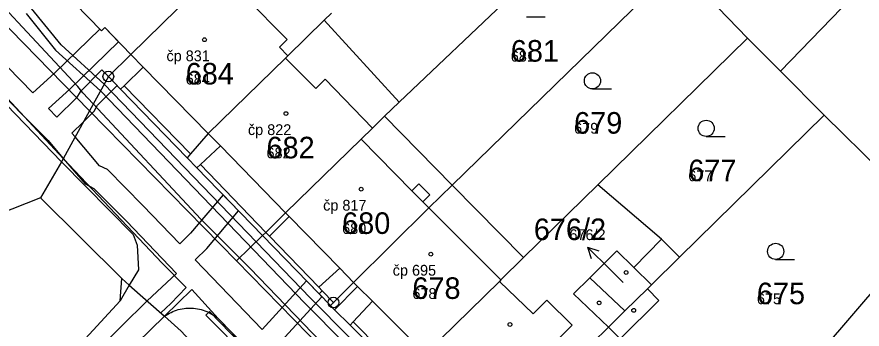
# Model space of a CAD drawing. Extents: x -763628 to -761565, y -976033 to -973833.
# Drawn here: x -762200.4 to -762122, y -974541.7 to -974512.8 of the extents above; entities that cross this region are included whole.
import ezdxf

# ---------------------------------------------------------------- set-up
doc = ezdxf.new("R2010")
doc.units = 0
for name, color, linetype in [('KN_cisla parcel 1000', 7, 'Continuous'), ('KN_cisla parcel 500', 7, 'Continuous'), ('KN_cisla parcel znacky', 7, 'Continuous'), ('KN_cisla popisna 500', 7, 'Continuous'), ('KN_hranice parcel', 7, 'Continuous'), ('KN_vecna bremena', 7, 'Continuous'), ('KN_vnitrni kresba parcel', 7, 'Continuous'), ('KN_znacky bodu BP', 7, 'Continuous'), ('KN_znacky budov', 7, 'Continuous'), ('KN_znacky kultur', 7, 'Continuous')]:
    doc.layers.add(name, color=color, linetype=linetype)

msp = doc.modelspace()

# ---------------------------------------------------------------- linework, layer by layer
at = {"layer": 'KN_cisla parcel znacky'}
for p, q in [((-762145.35, -974536.23), (-762147.472, -974534.108)), ((-762147.472, -974534.108), (-762146.41, -974534.462)), ((-762147.472, -974534.108), (-762147.118, -974535.17)), ((-762144.18, -974537.39), (-762145.35, -974536.23))]:
    msp.add_line(p, q, dxfattribs=at)
at = {"layer": 'KN_hranice parcel'}
for p, q in [((-762145.19, -974501.92), (-762164.94, -974520.66)), ((-762129.59, -974517.78), (-762119.51, -974507.39)), ((-762139.09, -974507.96), (-762160.01, -974528.36)), ((-762136.74, -974510.49), (-762132.64, -974514.72)), ((-762171.2, -974512.4), (-762171.88, -974513.06)), ((-762164.94, -974520.66), (-762171.88, -974513.06)), ((-762132.64, -974514.72), (-762146.5, -974528.33)), ((-762132.64, -974514.72), (-762129.59, -974517.78)), ((-762189.8, -974516.24), (-762191.88, -974518.29)), ((-762129.59, -974517.78), (-762125.54, -974521.87)), ((-762164.94, -974520.66), (-762166.28, -974521.98)), ((-762160.01, -974528.36), (-762166.28, -974521.98)), ((-762125.54, -974521.87), (-762138.95, -974535.06)), ((-762125.54, -974521.87), (-762120.12, -974527.23)), ((-762196.23, -974526.19), (-762198.17, -974529.54)), ((-762153.4, -974535.09), (-762160.01, -974528.36)), ((-762146.5, -974528.33), (-762153.4, -974535.09)), ((-762198.17, -974529.54), (-762223.04, -974539.44)), ((-762190.63, -974537.03), (-762198.17, -974529.54)), ((-762138.95, -974535.06), (-762141.54, -974537.62)), ((-762119.2, -974536.03), (-762134.17, -974553.51)), ((-762141.92, -974537.99), (-762144, -974540.04)), ((-762141.54, -974537.62), (-762141.92, -974537.99))]:
    msp.add_line(p, q, dxfattribs=at)
for points in [[(-762236.22, -974463.78), (-762226.18, -974485.62), (-762217.49, -974504.16), (-762196.23, -974526.19)], [(-762201.19, -974505.11), (-762192.52, -974514.04), (-762192.2, -974513.74), (-762189.8, -974516.24)], [(-762189.8, -974516.24), (-762182.62, -974509.19), (-762181.34, -974508.05)], [(-762171.88, -974513.06), (-762175.25, -974516.37), (-762175.46, -974516.59), (-762182.62, -974523.57), (-762184.27, -974525.47), (-762184.59, -974525.84)], [(-762191.88, -974518.29), (-762193.63, -974521.46), (-762196.23, -974526.19)], [(-762191.88, -974518.29), (-762190.74, -974519.46), (-762184.59, -974525.84)], [(-762166.28, -974521.98), (-762167.4, -974523.08), (-762168.45, -974524.11), (-762175.45, -974530.94), (-762177.27, -974532.75), (-762177.58, -974533.05)], [(-762184.59, -974525.84), (-762183.69, -974526.76), (-762177.58, -974533.05)], [(-762160.01, -974528.36), (-762162.18, -974530.47), (-762169.15, -974537.41), (-762171.02, -974539.25), (-762171.3, -974539.53)], [(-762138.95, -974535.06), (-762140.6, -974533.39), (-762146.5, -974528.33)], [(-762177.58, -974533.05), (-762172.35, -974538.44), (-762171.3, -974539.53)], [(-762153.4, -974535.09), (-762155.49, -974537.16), (-762155.64, -974537.31), (-762162.5, -974544.01), (-762164.38, -974545.85), (-762164.71, -974546.17)], [(-762144, -974540.04), (-762147.26, -974536.95), (-762144.76, -974534.47), (-762143.17, -974536.02), (-762141.54, -974537.62)], [(-762206.56, -974556.23), (-762190.8, -974539.09), (-762190.63, -974537.03)], [(-762190.63, -974537.03), (-762189.94, -974537.64), (-762186.68, -974540.53), (-762185.12, -974541.91)], [(-762134.17, -974553.51), (-762144.02, -974543.06), (-762144.45, -974542.61), (-762140.85, -974539.07), (-762141.92, -974537.99)], [(-762171.3, -974539.53), (-762170.91, -974539.92), (-762169.48, -974541.36), (-762164.71, -974546.17)], [(-762144, -974540.04), (-762145.52, -974541.53), (-762147.04, -974543.02), (-762148.48, -974544.45), (-762155.43, -974551.2), (-762157.28, -974553.02), (-762157.6, -974553.34)]]:
    msp.add_lwpolyline(points, dxfattribs=at)
at = {"layer": 'KN_vecna bremena'}
for points in [[(-762217.59, -974502.68), (-762196.06, -974525.88), (-762186.88, -974535.6), (-762184.68, -974537.86), (-762186.09, -974539.34), (-762187.03, -974540.22), (-762186.68, -974540.53), (-762185.12, -974541.91), (-762176.94, -974550.78), (-762171.68, -974556.13), (-762169.8, -974558.04), (-762169.58, -974558.26), (-762164.15, -974563.73), (-762162.99, -974564.9), (-762162.7, -974565.2), (-762161.62, -974566.3), (-762159.27, -974568.71), (-762151.74, -974576.15), (-762145.7, -974582.29), (-762139.78, -974588.67), (-762136.35, -974592.18)], [(-762124.12, -974592.4), (-762129.34, -974586.94), (-762156.48, -974559.2), (-762178.73, -974536.11), (-762183.31, -974531.51), (-762193.28, -974520.82), (-762194.23, -974519.8), (-762194.71, -974519.23), (-762206.25, -974506.82)], [(-762176.2, -974543.22), (-762172.08, -974538.72), (-762172.35, -974538.44), (-762173.5, -974537.25), (-762177.62, -974541.75), (-762183.84, -974535.28), (-762182.76, -974534.23), (-762179.82, -974530.74), (-762181.25, -974529.27), (-762184.26, -974532.83), (-762185.24, -974533.8), (-762188.68, -974530.24), (-762191.96, -974526.93), (-762192.7, -974526.56), (-762194.97, -974523.9), (-762195.26, -974523.55), (-762194.21, -974522.52), (-762193.2, -974521.52), (-762192.87, -974520.96), (-762191.06, -974519.13), (-762191.88, -974518.29), (-762192.49, -974517.67), (-762194.49, -974519.7), (-762194.82, -974520.26), (-762196.64, -974522.05), (-762197.44, -974521.25), (-762195.46, -974519.47), (-762190.93, -974515.06), (-762192.2, -974513.74), (-762192.52, -974514.04), (-762192.66, -974513.9), (-762196.86, -974517.97), (-762198.88, -974519.79), (-762208.34, -974510.11)], [(-762209.88, -974511.57), (-762199.71, -974521.97), (-762197.46, -974524.24), (-762196.06, -974525.88), (-762194.04, -974528.26), (-762193.22, -974528.67), (-762190.2, -974531.72), (-762185.55, -974536.55), (-762188.28, -974539.11), (-762197.81, -974548.5), (-762206.48, -974556.8)], [(-762121.48, -974586.26), (-762125.05, -974586.62), (-762126.23, -974586.47), (-762128.55, -974584.51), (-762135.4, -974577.57), (-762145.9, -974566.77), (-762151.59, -974560.75), (-762158.27, -974553.85), (-762173.17, -974538.83), (-762192.26, -974518.99), (-762196.25, -974515.36), (-762198.99, -974511.99)], [(-762199.51, -974512.45), (-762196.77, -974515.84), (-762192.62, -974519.62), (-762173.67, -974539.31), (-762158.77, -974554.35), (-762152.09, -974561.23), (-762146.4, -974567.25), (-762135.9, -974578.05), (-762129.03, -974585.03), (-762126.53, -974587.13), (-762125.2, -974587.34), (-762124.42, -974587.26), (-762121.51, -974586.97)], [(-762205.06, -974558.28), (-762197.14, -974550.71), (-762196.76, -974551.14), (-762195.31, -974549.71), (-762195.67, -974549.3), (-762186.68, -974540.53), (-762184.13, -974538.05), (-762181.7, -974540.74), (-762169.94, -974552.8)]]:
    msp.add_lwpolyline(points, dxfattribs=at)
msp.add_lwpolyline([(-762160.34, -974562.96), (-762150.82, -974572.71), (-762158.42, -974565.19), (-762166.05, -974557.27), (-762175.1, -974548.24), (-762182.84, -974540.42), (-762182.52, -974540.09)], close=True, dxfattribs=at)
at = {"layer": 'KN_vnitrni kresba parcel'}
for p, q in [((-762179.2, -974510.91), (-762175.32, -974514.87)), ((-762193.63, -974521.46), (-762202.47, -974512.42)), ((-762175.32, -974514.87), (-762176.03, -974515.57)), ((-762188.65, -974517.41), (-762189.8, -974516.24)), ((-762176.03, -974515.57), (-762175.25, -974516.37)), ((-762175.46, -974516.59), (-762172.66, -974519.41)), ((-762190.42, -974519.14), (-762188.65, -974517.41)), ((-762188.65, -974517.41), (-762182.62, -974523.57)), ((-762172.66, -974519.41), (-762171.78, -974518.53)), ((-762171.78, -974518.53), (-762167.4, -974523.08)), ((-762190.42, -974519.14), (-762190.74, -974519.46)), ((-762184.27, -974525.47), (-762190.42, -974519.14)), ((-762180, -974535.39), (-762193.63, -974521.46)), ((-762181.5, -974524.72), (-762182.62, -974523.57)), ((-762163.74, -974528.89), (-762168.45, -974524.11)), ((-762183.34, -974526.44), (-762181.5, -974524.72)), ((-762175.45, -974530.94), (-762181.5, -974524.72)), ((-762189.59, -974532.95), (-762196.23, -974526.19)), ((-762183.69, -974526.76), (-762183.34, -974526.44)), ((-762177.27, -974532.75), (-762183.34, -974526.44)), ((-762163.74, -974528.89), (-762163.09, -974528.25)), ((-762163.09, -974528.25), (-762162.09, -974529.27)), ((-762162.74, -974529.9), (-762163.74, -974528.89)), ((-762162.09, -974529.27), (-762162.74, -974529.9)), ((-762162.18, -974530.47), (-762162.74, -974529.9)), ((-762175.11, -974531.29), (-762175.45, -974530.94)), ((-762155.49, -974537.16), (-762162.18, -974530.47)), ((-762176.94, -974533.1), (-762175.11, -974531.29)), ((-762170.44, -974536.08), (-762175.11, -974531.29)), ((-762176.94, -974533.1), (-762177.27, -974532.75)), ((-762189.59, -974532.95), (-762189.21, -974533.92)), ((-762177.58, -974533.05), (-762180, -974535.39)), ((-762172.38, -974537.84), (-762176.94, -974533.1)), ((-762143.17, -974536.02), (-762140.6, -974533.39)), ((-762189.21, -974533.92), (-762189.09, -974536.22)), ((-762128.34, -974588.18), (-762180, -974535.39)), ((-762189.09, -974536.22), (-762189.94, -974537.64)), ((-762170.44, -974536.08), (-762172.38, -974537.84)), ((-762169.15, -974537.41), (-762170.44, -974536.08)), ((-762168.79, -974537.76), (-762169.15, -974537.41)), ((-762155.64, -974537.31), (-762152.51, -974540.3)), ((-762147.26, -974536.95), (-762148.77, -974538.45)), ((-762189.94, -974537.64), (-762190.8, -974539.09)), ((-762172.06, -974538.17), (-762172.38, -974537.84)), ((-762172.35, -974538.44), (-762172.06, -974538.17)), ((-762171.02, -974539.25), (-762172.06, -974538.17)), ((-762168.79, -974537.76), (-762170.91, -974539.92)), ((-762167.41, -974539.13), (-762168.79, -974537.76)), ((-762148.77, -974538.45), (-762145.52, -974541.53)), ((-762167.41, -974539.13), (-762169.2, -974541.06)), ((-762162.5, -974544.01), (-762167.41, -974539.13)), ((-762151.24, -974539.04), (-762152.51, -974540.3)), ((-762148.9, -974541.35), (-762151.24, -974539.04)), ((-762181.7, -974540.74), (-762135.9, -974587.72)), ((-762169.2, -974541.06), (-762169.48, -974541.36)), ((-762169.2, -974541.06), (-762164.38, -974545.85)), ((-762150.29, -974542.74), (-762148.9, -974541.35)), ((-762144.45, -974542.61), (-762145.52, -974541.53))]:
    msp.add_line(p, q, dxfattribs=at)
msp.add_lwpolyline([(-762186.68, -974540.53), (-762186.532, -974540.429), (-762186.38, -974540.334), (-762186.224, -974540.246), (-762186.065, -974540.165), (-762185.901, -974540.091), (-762185.735, -974540.025), (-762185.566, -974539.966), (-762185.394, -974539.914), (-762185.221, -974539.871), (-762185.045, -974539.835), (-762184.868, -974539.806), (-762184.69, -974539.786), (-762184.512, -974539.774), (-762184.333, -974539.769), (-762184.154, -974539.773), (-762183.975, -974539.785), (-762183.797, -974539.804), (-762183.62, -974539.831), (-762183.444, -974539.866), (-762183.27, -974539.909), (-762183.099, -974539.96), (-762182.929, -974540.018), (-762182.763, -974540.084), (-762182.599, -974540.157), (-762182.439, -974540.237), (-762182.282, -974540.324), (-762182.13, -974540.418), (-762181.982, -974540.519), (-762181.839, -974540.626), (-762181.7, -974540.74)], dxfattribs=at)
at = {"layer": 'KN_znacky bodu BP'}
for centre, radius in [((-762191.88, -974518.29), 0.5), ((-762191.88, -974518.29), 0.0303), ((-762171.02, -974539.25), 0.5), ((-762171.02, -974539.25), 0.0303)]:
    msp.add_circle(centre, radius, dxfattribs=at)
at = {"layer": 'KN_znacky budov'}
for centre in [(-762182.967, -974514.879), (-762175.417, -974521.729), (-762168.447, -974528.739), (-762161.997, -974534.769), (-762143.897, -974536.469), (-762146.397, -974539.289), (-762143.187, -974539.979), (-762154.657, -974541.289)]:
    msp.add_circle(centre, 0.175, dxfattribs=at)
at = {"layer": 'KN_znacky kultur'}
for p, q in [((-762153.133, -974512.76), (-762151.383, -974512.76)), ((-762147.013, -974519.44), (-762145.263, -974519.44)), ((-762136.473, -974523.85), (-762134.723, -974523.85)), ((-762130.033, -974535.26), (-762128.283, -974535.26))]:
    msp.add_line(p, q, dxfattribs=at)
for centre in [(-762147.013, -974518.69), (-762136.473, -974523.1), (-762130.033, -974534.51)]:
    msp.add_circle(centre, 0.75, dxfattribs=at)

# ---------------------------------------------------------------- texts
at = {"layer": 'KN_cisla parcel 1000'}
for s, p in [('681', (-762154.58, -974516.91)), ('684', (-762184.71, -974519.03)), ('679', (-762148.71, -974523.59)), ('682', (-762177.22, -974525.88)), ('677', (-762138.13, -974528)), ('680', (-762170.21, -974532.89)), ('676/2', (-762152.446, -974533.463)), ('678', (-762163.7, -974538.92)), ('675', (-762131.77, -974539.41))]:
    msp.add_text(s, height=2, dxfattribs=at).set_placement(p)
at = {"layer": 'KN_cisla parcel 500'}
for s, p in [('681', (-762154.58, -974516.91)), ('684', (-762184.71, -974519.03)), ('679', (-762148.71, -974523.59)), ('682', (-762177.22, -974525.88)), ('677', (-762138.13, -974528)), ('680', (-762170.21, -974532.89)), ('676/2', (-762149.146, -974533.463)), ('678', (-762163.7, -974538.92)), ('675', (-762131.77, -974539.41))]:
    msp.add_text(s, height=1, dxfattribs=at).set_placement(p)
at = {"layer": 'KN_cisla popisna 500'}
for s, p in [('čp 831', (-762186.491, -974516.871)), ('čp 822', (-762178.941, -974523.721)), ('čp 817', (-762171.971, -974530.731)), ('čp 695', (-762165.521, -974536.761))]:
    msp.add_text(s, height=1, dxfattribs=at).set_placement(p)

doc.saveas('drawing.dxf')
